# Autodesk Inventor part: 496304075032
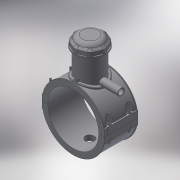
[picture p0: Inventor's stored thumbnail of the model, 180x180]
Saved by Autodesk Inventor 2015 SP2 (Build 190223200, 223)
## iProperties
Created: 2017-07
Part Number: 496304075032
Material: Generic
Description: PLASSON TAPPING SADDLE 75x32
Document SubType Name: Modeling
Designer: KIM
Mass: 671.723 g
Surface Area: 1655.68 cm^2
Volume: 671.723 cm^3
Density: 1 g/cm^3
Appearance: Default
Author: KIM
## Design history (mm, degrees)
derived "496304.ipt"
feature "Solid1::496304.ipt"
feature "Solid2::496304.ipt"
feature "Solid4::496304.ipt"
feature "Solid5::496304.ipt"
tag "TaggingFeature1"
body "Solid1"
body "Solid2"
other parameters: "d0" = 75, "d2" = 117, "d3" = 18.75, "d4" = 118, "d5" = 0, "d6" = 0.1, "d8" = 0, "d19" = 6, "d20" = 6, "d21" = 70.8, "d23" = 0, "d24" = 35.4, "d26" = 0, "d29" = 3, "d30" = 25, "d31" = 6, "d32" = 0, "d33" = 0, "d34" = 0.6, "d40" = 50.7, "d41" = 67.5, "d43" = 0, "d45" = 0, "d47" = 119.55, "d70" = 15, "d72" = 0, "d73" = 6, "d75" = 5, "d76" = 0, "d77" = 3.75, "d78" = 67.5, "d79" = 15, "d80" = 47.2, "d82" = 5 deg, "d84" = 4, "d85" = 14, "d86" = 0, "d87" = 3, "d88" = 0, "d89" = 1, "d90" = 1, "d91" = 94.4, "d92" = 0, "d93" = 0.5, "d94" = 39.47368, "d96" = 99.45, "d97" = 2.36, "d98" = 0, "d102" = 0.75, "d120" = 140 deg, "d121" = 24.228, "d122" = 20 deg, "d123" = 195, "d124" = 58.5, "d126" = 0, "d143" = 77.25, "d145" = 17.30769, "d149" = 1.125, "d150" = 19.03846, "d153" = 118, "d154" = 0, "d156" = 48.75, "d157" = 160 deg, "d159" = 4.5, "d161" = 1.125, "d162" = 70.8, "d163" = 0, "d164" = 37.5, "d167" = 7.5, "d168" = 47.56098, "d170" = 3.375, "d172" = 0, "d173" = 1, "d175" = 37.5, "d176" = 20 deg, "d177" = 5.25, "d178" = 22.5, "d180" = 0, "d183" = 9, "d184" = 4.2, "d185" = 38.35, "d186" = 38.35, "d187" = 48.75, "d188" = 6.75, "d189" = 5.25, "d190" = 0, "d191" = 73.125, "d193" = 6.3, "d194" = 4.13, "d195" = 90 deg, "d197" = 0, "d199" = 0, "d200" = 11.25, "d202" = 0, "d203" = 177, "d204" = 64.125, "d205" = 47.25, "d206" = 57.375, "d207" = 132.75, "d208" = 138.06, "d209" = 164.61, "d210" = 58.05, "d211" = 67.5, "d212" = 54, "d213" = 36, "d216" = 0, "d217" = 7.5, "d218" = 7.5, "d219" = 1.5, "d222" = 75, "d224" = 0, "d230" = 4.5, "d233" = 6, "d236" = 58.5, "d237" = 35.4, "d238" = 6.02433, "d240" = 35.4, "d241" = 35.4, "d242" = 35.4, "d243" = 6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
